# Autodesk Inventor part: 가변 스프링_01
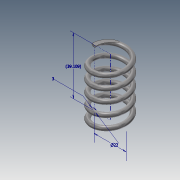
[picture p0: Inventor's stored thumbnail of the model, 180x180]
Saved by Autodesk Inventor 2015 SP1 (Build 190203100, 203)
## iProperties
Created: 2015-05
Part Number: 가변 스프링_01
Material: 강철, 탄소
Document SubType Name: Modeling
Designer: jckim
Density: 7.85 g/cm^3
Appearance: 반연마
Mass: 18.8593 g
Surface Area: 32.5658 cm^2
Volume: 2.40246 cm^3
Author: jckim
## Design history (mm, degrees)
sketch "스케치1"
  geometry: L1 (0, 0)-(11, 0); L2 (11, 0)-(11, 39.109); L3 (11, 39.109)-(0, 39.109); L4 (0, 39.109)-(0, 0); C1 r 1.5 at (11, 0)
  constraints: 8 end point, 2 parallel, 1 centre point, 1 coincident, 1 horizontal, 1 perpendicular
  dimensions: "d0" = 3 diameter of C1; "d1" = 22 diameter of L2 L4; "d3" = 39.10851 distance of L1.end L2.end (derived)
feature "코일1" pitch "d4" = 10; turns "d6" = 5; dims "d5" = 39.10851 (= d3), "d7" = 0, angle "d8" = 90 deg, angle "d9" = 90 deg, "d10" = 0, "d11" = 0
sketch "스케치2"
  geometry: L1 (-12.5, 0)-(-9.5, 0) reference; 1 further point
  constraints: 1 horizontal alignment
extrude "돌출1" cut sketch "스케치2" stored distance "d12" = 10; taper "d13" = 0 deg
node "작업 평면1"
sketch "스케치3"
  geometry: L1 (1.5, 0)-(-1.5, 0) reference; 1 further point
  constraints: 1 horizontal alignment
extrude "돌출2" cut sketch "스케치3" stored distance "d15" = 10; taper "d16" = 0 deg
node "솔리드1"
node "절단 모서리 투영1"
node "절단 모서리 투영2"
other parameters: "d14" = 0
